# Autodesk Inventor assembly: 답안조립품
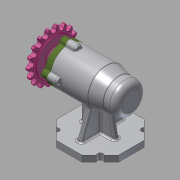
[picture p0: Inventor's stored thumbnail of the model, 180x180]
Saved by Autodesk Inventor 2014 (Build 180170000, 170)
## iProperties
Created: 2021-01
Part Number: 답안조립품
Document SubType Name: Assembly
Designer: kh
Author: kh
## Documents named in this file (12)
- C:\Users\kh\Desktop\710106V1017\답안조립품.iam
- C:\Users\kh\Desktop\710106V1017\본체.ipt
- C:\Users\kh\Desktop\710106V1017\멈춤나사 M3.ipt
- C:\Users\kh\Desktop\710106V1017\베어링 6004.ipt
- C:\Users\kh\Desktop\710106V1017\베어링 51202.ipt
- C:\Users\kh\Desktop\710106V1017\볼트 M4.ipt
- C:\Users\kh\Desktop\710106V1017\스프로킷.ipt
- C:\Users\kh\Desktop\710106V1017\어댑터슬리브.ipt
- C:\Users\kh\Desktop\710106V1017\오일 실.ipt
- C:\Users\kh\Desktop\710106V1017\축.ipt
- C:\Users\kh\Desktop\710106V1017\커버.ipt
- C:\Users\kh\Desktop\710106V1017\키 5 x 5 x 14.ipt
